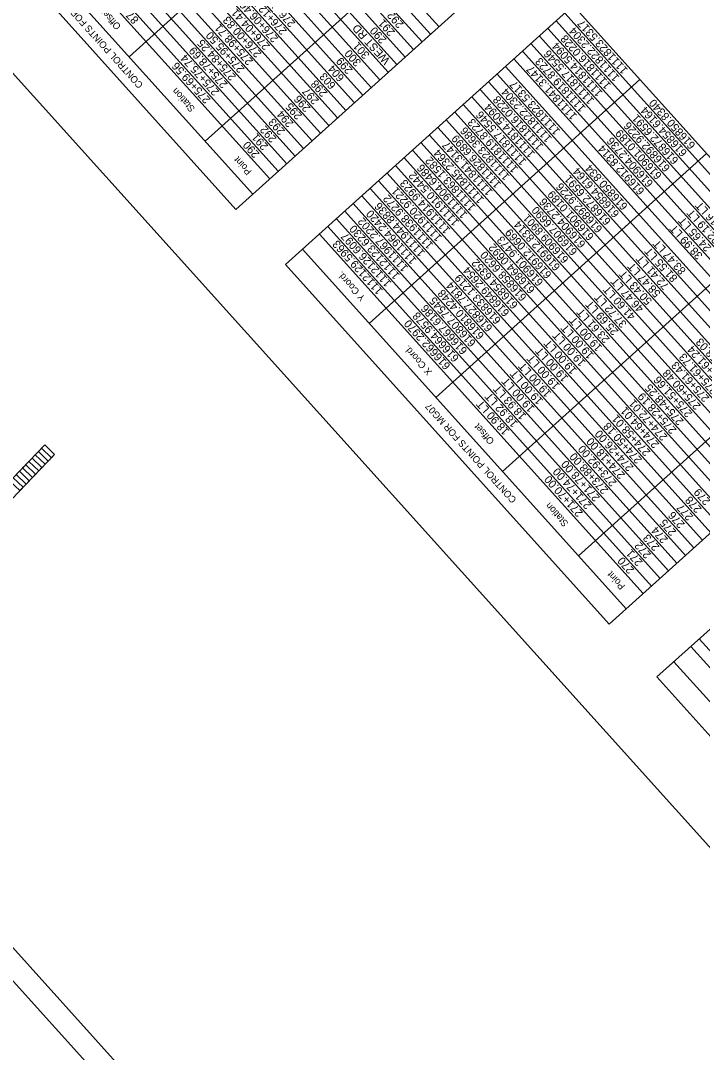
# Model space of a CAD drawing. Extents: x 1111534 to 1112511, y 616515 to 617559.
# Drawn here: x 1111860 to 1112159.5, y 616756 to 617209.1 of the extents above; entities that cross this region are included whole.
import ezdxf

# ---------------------------------------------------------------- set-up
doc = ezdxf.new("R2010")
doc.units = 0
for name, color, linetype in [('ANNOTATION', 7, 'Continuous'), ('BORDER', 7, 'Continuous'), ('CLIPS', 7, 'Continuous'), ('H_V CONTROLS', 7, 'Continuous'), ('PLOT BOUNDARY', 7, 'Continuous'), ('SIGNS TRAFFIC', 7, 'Continuous')]:
    doc.layers.add(name, color=color, linetype=linetype)

msp = doc.modelspace()

# ---------------------------------------------------------------- linework, layer by layer
at = {"layer": 'BORDER'}
msp.add_line((1111547.09, 617145.67), (1112082.4, 616551.15), dxfattribs=at)
at = {"layer": 'CLIPS'}
msp.add_lwpolyline([(1112472.55, 616902.44), (1111970.7, 617459.8), (1111771.54, 617280.48), (1112273.39, 616723.12)], close=True, dxfattribs=at)
at = {"layer": 'H_V CONTROLS'}
for p, q in [((1112043.76, 617206.51), (1111901.57, 617364.42)), ((1112040.05, 617203.16), (1111897.86, 617361.08)), ((1112032.62, 617196.47), (1111890.43, 617354.39)), ((1112036.33, 617199.81), (1111894.14, 617357.73)), ((1112028.9, 617193.12), (1111886.71, 617351.04)), ((1112025.19, 617189.78), (1111883, 617347.7)), ((1112017.75, 617183.09), (1111875.56, 617341)), ((1112021.47, 617186.43), (1111879.28, 617344.35)), ((1112014.04, 617179.74), (1111871.85, 617337.66)), ((1112010.32, 617176.39), (1111868.13, 617334.31)), ((1112002.89, 617169.7), (1111860.7, 617327.62)), ((1112006.61, 617173.05), (1111864.42, 617330.97)), ((1111999.18, 617166.36), (1111856.99, 617324.28)), ((1111995.46, 617163.01), (1111853.27, 617320.93)), ((1111988.03, 617156.32), (1111845.84, 617314.24)), ((1111991.74, 617159.67), (1111849.55, 617317.58)), ((1111984.31, 617152.97), (1111842.12, 617310.89)), ((1111980.6, 617149.63), (1111838.41, 617307.55)), ((1111973.17, 617142.94), (1111830.98, 617300.86)), ((1111976.88, 617146.28), (1111834.69, 617304.2)), ((1111969.45, 617139.59), (1111827.26, 617297.51)), ((1111962.02, 617132.9), (1111819.83, 617290.82)), ((1111954.59, 617126.21), (1111812.4, 617284.13)), ((1111907.65, 617193.28), (1112004.26, 617280.27)), ((1111941.11, 617156.12), (1112037.72, 617243.11)), ((1111954.59, 617126.21), (1112058.63, 617219.89)), ((1111976.39, 617101.99), (1112102.73, 617215.74)), ((1112244.92, 617057.82), (1112102.73, 617215.74)), ((1112241.2, 617054.48), (1112099.01, 617212.4)), ((1112233.77, 617047.79), (1112091.58, 617205.71)), ((1112237.49, 617051.13), (1112095.3, 617209.05)), ((1112230.06, 617044.44), (1112087.87, 617202.36)), ((1112226.34, 617041.1), (1112084.15, 617199.01)), ((1112218.91, 617034.4), (1112076.72, 617192.32)), ((1112222.62, 617037.75), (1112080.43, 617195.67)), ((1112215.19, 617031.06), (1112073, 617188.98)), ((1112013.1, 617076.17), (1112132, 617183.23)), ((1112207.76, 617024.37), (1112065.57, 617182.29)), ((1112211.48, 617027.71), (1112069.29, 617185.63)), ((1112204.05, 617021.02), (1112061.86, 617178.94)), ((1112200.33, 617017.68), (1112058.14, 617175.59)), ((1112192.9, 617010.99), (1112050.71, 617168.9)), ((1112196.61, 617014.33), (1112054.42, 617172.25)), ((1112189.18, 617007.64), (1112046.99, 617165.56)), ((1112185.47, 617004.29), (1112043.28, 617162.21)), ((1112178.04, 616997.6), (1112035.85, 617155.52)), ((1112181.75, 617000.95), (1112039.56, 617158.87)), ((1112174.32, 616994.26), (1112032.13, 617152.18)), ((1112042.37, 617043.66), (1112161.28, 617150.72)), ((1112170.6, 616990.91), (1112028.41, 617148.83)), ((1112163.17, 616984.22), (1112020.98, 617142.14)), ((1112166.89, 616987.57), (1112024.7, 617145.48)), ((1112159.46, 616980.87), (1112017.27, 617138.79)), ((1112155.74, 616977.53), (1112013.55, 617135.45)), ((1112148.31, 616970.84), (1112006.12, 617128.76)), ((1112152.03, 616974.18), (1112009.84, 617132.1)), ((1112144.59, 616967.49), (1112002.4, 617125.41)), ((1112137.16, 616960.8), (1111994.97, 617118.72)), ((1112140.88, 616964.15), (1111998.69, 617122.06)), ((1112133.45, 616957.45), (1111991.26, 617115.37)), ((1112071.65, 617011.14), (1112190.55, 617118.2)), ((1112126.02, 616950.76), (1111983.83, 617108.68)), ((1112118.58, 616944.07), (1111976.39, 617101.99)), ((1112105.11, 616973.99), (1112224.01, 617081.05)), ((1112118.58, 616944.07), (1112244.92, 617057.82)), ((1112139.49, 616920.85), (1112276.98, 617044.64)), ((1112300.26, 616779.66), (1112158.07, 616937.58)), ((1112296.55, 616776.31), (1112154.36, 616934.23)), ((1112289.12, 616769.62), (1112146.93, 616927.54)), ((1112281.68, 616762.93), (1112139.49, 616920.85))]:
    msp.add_line(p, q, dxfattribs=at)
at = {"layer": 'PLOT BOUNDARY'}
msp.add_lwpolyline([(1112510.99, 616882.61), (1111942.23, 617514.28), (1111533.5, 617146.26), (1112102.26, 616514.59)], close=True, dxfattribs=at)
at = {"layer": 'SIGNS TRAFFIC'}
for p, q in [((1111870.58, 617022.74), (1111844.26, 616995.33)), ((1111848.59, 616991.17), (1111874.91, 617018.58))]:
    msp.add_line(p, q, dxfattribs=at)
for points in [[(1111872.14, 617015.7), (1111867.81, 617019.85), (1111866.42, 617018.41), (1111870.75, 617014.26)], [(1111874.91, 617018.58), (1111870.58, 617022.74), (1111869.19, 617021.3), (1111873.52, 617017.14)], [(1111869.37, 617012.81), (1111865.03, 617016.97), (1111863.65, 617015.52), (1111867.98, 617011.37)], [(1111863.83, 617007.04), (1111859.5, 617011.2), (1111858.11, 617009.75), (1111862.44, 617005.6)], [(1111866.6, 617009.93), (1111862.27, 617014.08), (1111860.88, 617012.64), (1111865.21, 617008.48)], [(1111861.06, 617004.16), (1111856.73, 617008.31), (1111855.34, 617006.87), (1111859.67, 617002.71)]]:
    msp.add_lwpolyline(points, close=True, dxfattribs=at)

# ---------------------------------------------------------------- texts
at = {"layer": 'ANNOTATION'}
for s, height, p in [('276+15.61', 3.45, (1111980.89, 617208.1)), ('87.09 LT', 3.516, (1111912.15, 617209.58)), ('276+12.55', 3.45, (1111977.16, 617204.74)), ('276+04.41', 3.516, (1111969.76, 617198.08)), ('276+06.46', 3.516, (1111973.47, 617201.42)), ('276+00.83', 3.516, (1111966.07, 617194.76)), ('291', 3.516, (1112024.63, 617204.23)), ('292', 3.516, (1112028.49, 617207.7)), ('275+98.71', 3.516, (1111962.38, 617191.44)), ('WEST RD', 3.516, (1112022.49, 617191.79)), ('290', 3.516, (1112020.94, 617200.9)), ('1111822.2304', 3.5156, (1112123.31, 617184.26)), ('1111823.5317', 3.5156, (1112126.97, 617187.55)), ('275+84.25', 3.516, (1111954.85, 617184.65)), ('275+95.50', 3.516, (1111958.6, 617188.03)), ('1111816.0228', 3.5156, (1112119.56, 617180.88)), ('275+78.69', 3.516, (1111951.16, 617181.34)), ('300', 3.516, (1112009.83, 617190.89)), ('301', 3.516, (1112013.51, 617194.21)), ('1111817.5546', 3.5156, (1112112.18, 617174.24)), ('1111814.5094', 3.5156, (1112115.87, 617177.56)), ('275+75.74', 3.516, (1111947.48, 617178.02)), ('299', 3.516, (1112006.11, 617187.55)), ('1111819.8723', 3.5156, (1112108.43, 617170.86)), ('275+69.56', 3.516, (1111943.66, 617174.58)), ('604', 3.45, (1112002.4, 617184.21)), ('1111841.3147', 3.5156, (1112104.61, 617167.42)), ('298', 3.516, (1111994.99, 617177.53)), ('603', 3.45, (1111998.67, 617180.85)), ('297', 3.516, (1111991.27, 617174.18)), ('1111822.2304', 3.5156, (1112093.57, 617157.48)), ('1111823.5317', 3.5156, (1112097.23, 617160.77)), ('296', 3.516, (1111987.58, 617170.86)), ('1111816.0228', 3.5156, (1112089.84, 617154.12)), ('616850.8340', 3.5156, (1112156.65, 617154.58)), ('294', 3.516, (1111980.11, 617164.14)), ('295', 3.516, (1111983.9, 617167.55)), ('1111817.5546', 3.5156, (1112082.41, 617147.43)), ('1111814.5094', 3.5156, (1112086.13, 617150.78)), ('616854.6164', 3.5156, (1112153, 617151.29)), ('293', 3.516, (1111976.36, 617160.76)), ('1111819.8723', 3.5156, (1112078.75, 617144.14)), ('616892.9226', 3.5156, (1112145.56, 617144.59)), ('616872.6591', 3.5156, (1112149.24, 617147.91)), ('291', 3.516, (1111968.99, 617154.12)), ('292', 3.516, (1111972.68, 617157.44)), ('1111823.3686', 3.45, (1112075.07, 617140.82)), ('616901.0189', 3.5156, (1112141.87, 617141.27)), ('290', 3.516, (1111965.17, 617150.69)), ('1111841.3147', 3.5156, (1112067.62, 617134.12)), ('1111826.6899', 3.45, (1112071.27, 617137.4)), ('616904.2736', 3.5156, (1112138.11, 617137.89)), ('1111845.2364', 3.5156, (1112063.8, 617130.68)), ('616912.8314', 3.5156, (1112134.29, 617134.45)), ('1111904.6486', 3.5156, (1112056.49, 617124.09)), ('1111863.1582', 3.5156, (1112060.15, 617127.38)), ('1111910.5442', 3.5156, (1112052.84, 617120.8)), ('616872.6591', 3.5156, (1112119.52, 617121.15)), ('616854.6164', 3.5156, (1112123.26, 617124.51)), ('616850.834', 3.516, (1112126.92, 617127.8)), ('1111914.9923', 3.5156, (1112049.02, 617117.36)), ('616892.9226', 3.5156, (1112115.82, 617117.81)), ('1111938.9272', 3.5156, (1112041.57, 617110.66)), ('1111920.9221', 3.5156, (1112045.29, 617114.01)), ('616901.0189', 3.5156, (1112112.1, 617114.46)), ('1111944.8836', 3.5156, (1112037.85, 617107.31)), ('616904.2736', 3.5156, (1112108.44, 617111.17)), ('17.16 LT', 3.516, (1112171.07, 617116.25)), ('1111964.2420', 3.5156, (1112034.16, 617103.99)), ('616909.8901', 3.45, (1112100.96, 617104.43)), ('616907.6690', 3.45, (1112104.76, 617107.85)), ('22.19 LT', 3.516, (1112167.38, 617112.92)), ('1112123.6230', 3.5156, (1112026.79, 617097.35)), ('1111967.2202', 3.5156, (1112030.49, 617100.68)), ('616912.8314', 3.5156, (1112097.31, 617101.15)), ('38.99 LT', 3.516, (1112159.81, 617106.11)), ('24.65 LT', 3.516, (1112163.63, 617109.54)), ('1112126.6097', 3.5156, (1112023.11, 617094.04)), ('616901.9473', 3.5156, (1112089.83, 617094.42)), ('616912.0669', 3.5156, (1112093.49, 617097.71)), ('1112129.5963', 3.5156, (1112019.36, 617090.66)), ('616864.0692', 3.5156, (1112086.18, 617091.12)), ('83.47 LT', 3.516, (1112152.43, 617099.46)), ('616858.6620', 3.5156, (1112082.52, 617087.83)), ('72.41 LT', 3.516, (1112145.04, 617092.81)), ('81.55 LT', 3.516, (1112148.78, 617096.17)), ('616849.2654', 3.5156, (1112074.98, 617081.04)), ('616854.6352', 3.5156, (1112078.7, 617084.39)), ('58.47 LT', 3.516, (1112141.34, 617089.47)), ('616833.1219', 3.5156, (1112071.26, 617077.69)), ('50.43 LT', 3.516, (1112137.61, 617086.12)), ('616827.7814', 3.5156, (1112067.54, 617074.34)), ('41.60 LT', 3.45, (1112130.28, 617079.51)), ('46.47 LT', 3.516, (1112133.96, 617082.83)), ('616807.7545', 3.5156, (1112060.18, 617067.71)), ('616810.4248', 3.5156, (1112063.85, 617071.02)), ('37.72 LT', 3.45, (1112126.48, 617076.09)), ('616667.6186', 3.5156, (1112056.48, 617064.38)), ('25.69 LT', 3.516, (1112122.83, 617072.8)), ('616664.9578', 3.5156, (1112052.8, 617061.07)), ('19.00 LT', 3.516, (1112115.68, 617065.71)), ('23.61 LT', 3.516, (1112119.01, 617069.37)), ('616662.2970', 3.5156, (1112049.05, 617057.69)), ('19.00 LT', 3.516, (1112112.02, 617062.42)), ('19.00 LT', 3.516, (1112108.37, 617059.13)), ('275+58.03', 3.516, (1112173.8, 617053.41)), ('19.00 LT', 3.516, (1112100.83, 617052.34)), ('19.00 LT', 3.516, (1112104.55, 617055.69)), ('275+61.24', 3.516, (1112170.08, 617050.06)), ('19.00 LT', 3.516, (1112097.11, 617048.99)), ('275+61.73', 3.516, (1112166.43, 617046.77)), ('19.00 LT', 3.516, (1112093.38, 617045.63)), ('275+60.48', 3.45, (1112158.95, 617040.03)), ('275+61.43', 3.45, (1112162.74, 617043.45)), ('19.00 LT', 3.516, (1112086.02, 617039.01)), ('19.00 LT', 3.516, (1112089.7, 617042.31)), ('275+51.66', 3.516, (1112155.3, 617036.74)), ('18.93 LT', 3.516, (1112082.33, 617035.68)), ('275+48.25', 3.516, (1112151.48, 617033.31)), ('18.90 LT', 3.516, (1112074.89, 617028.98)), ('18.92 LT', 3.516, (1112078.65, 617032.36)), ('274+72.01', 3.516, (1112144.37, 617026.49)), ('275+28.19', 3.516, (1112148.31, 617029.48)), ('274+64.01', 3.516, (1112140.72, 617023.2)), ('274+58.01', 3.516, (1112136.9, 617019.76)), ('274+26.00', 3.516, (1112129.46, 617013.06)), ('274+50.18', 3.516, (1112133.18, 617016.41)), ('274+18.00', 3.516, (1112125.73, 617009.71)), ('273+88.00', 3.516, (1112118.37, 617003.08)), ('273+92.00', 3.516, (1112122.05, 617006.39)), ('271+78.00', 3.516, (1112114.68, 616999.75)), ('271+74.00', 3.516, (1112111, 616996.44)), ('271+70.00', 3.516, (1112107.24, 616993.06)), ('279', 3.516, (1112163.22, 616998.21)), ('278', 3.516, (1112159.4, 616994.77)), ('276', 3.516, (1112151.96, 616988.07)), ('277', 3.516, (1112155.68, 616991.42)), ('275', 3.516, (1112148.23, 616984.72)), ('273', 3.516, (1112140.87, 616978.09)), ('274', 3.516, (1112144.55, 616981.4)), ('272', 3.516, (1112137.18, 616974.76)), ('271', 3.516, (1112133.5, 616971.45)), ('270', 3.516, (1112129.74, 616968.07))]:
    msp.add_text(s, height=height, rotation=132, dxfattribs=at).set_placement(p)
at = {"layer": 'H_V CONTROLS'}
for s, p in [('CONTROL POINTS FOR MG08', (1111914.01, 617180.99)), ('Offset', (1111904.3, 617206.72)), ('Station', (1111936.81, 617170.61)), ('Point', (1111961.71, 617142.96)), ('Y Coord.', (1112011.63, 617087.51)), ('X Coord.', (1112040.91, 617055)), ('CONTROL POINTS FOR MG07', (1112078.01, 616998.85)), ('Offset', (1112068.29, 617024.58)), ('Station', (1112100.81, 616988.47)), ('Point', (1112125.71, 616960.82))]:
    msp.add_text(s, height=3, rotation=132, dxfattribs=at).set_placement(p)

doc.saveas('drawing.dxf')
